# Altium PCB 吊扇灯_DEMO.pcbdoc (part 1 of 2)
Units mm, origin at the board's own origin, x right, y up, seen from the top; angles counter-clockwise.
Board outline 117.71 x 71.75 mm, 2 copper layers (Top Layer, Bottom Layer); 71 components, 50 nets, 203 pads, 259 vias.
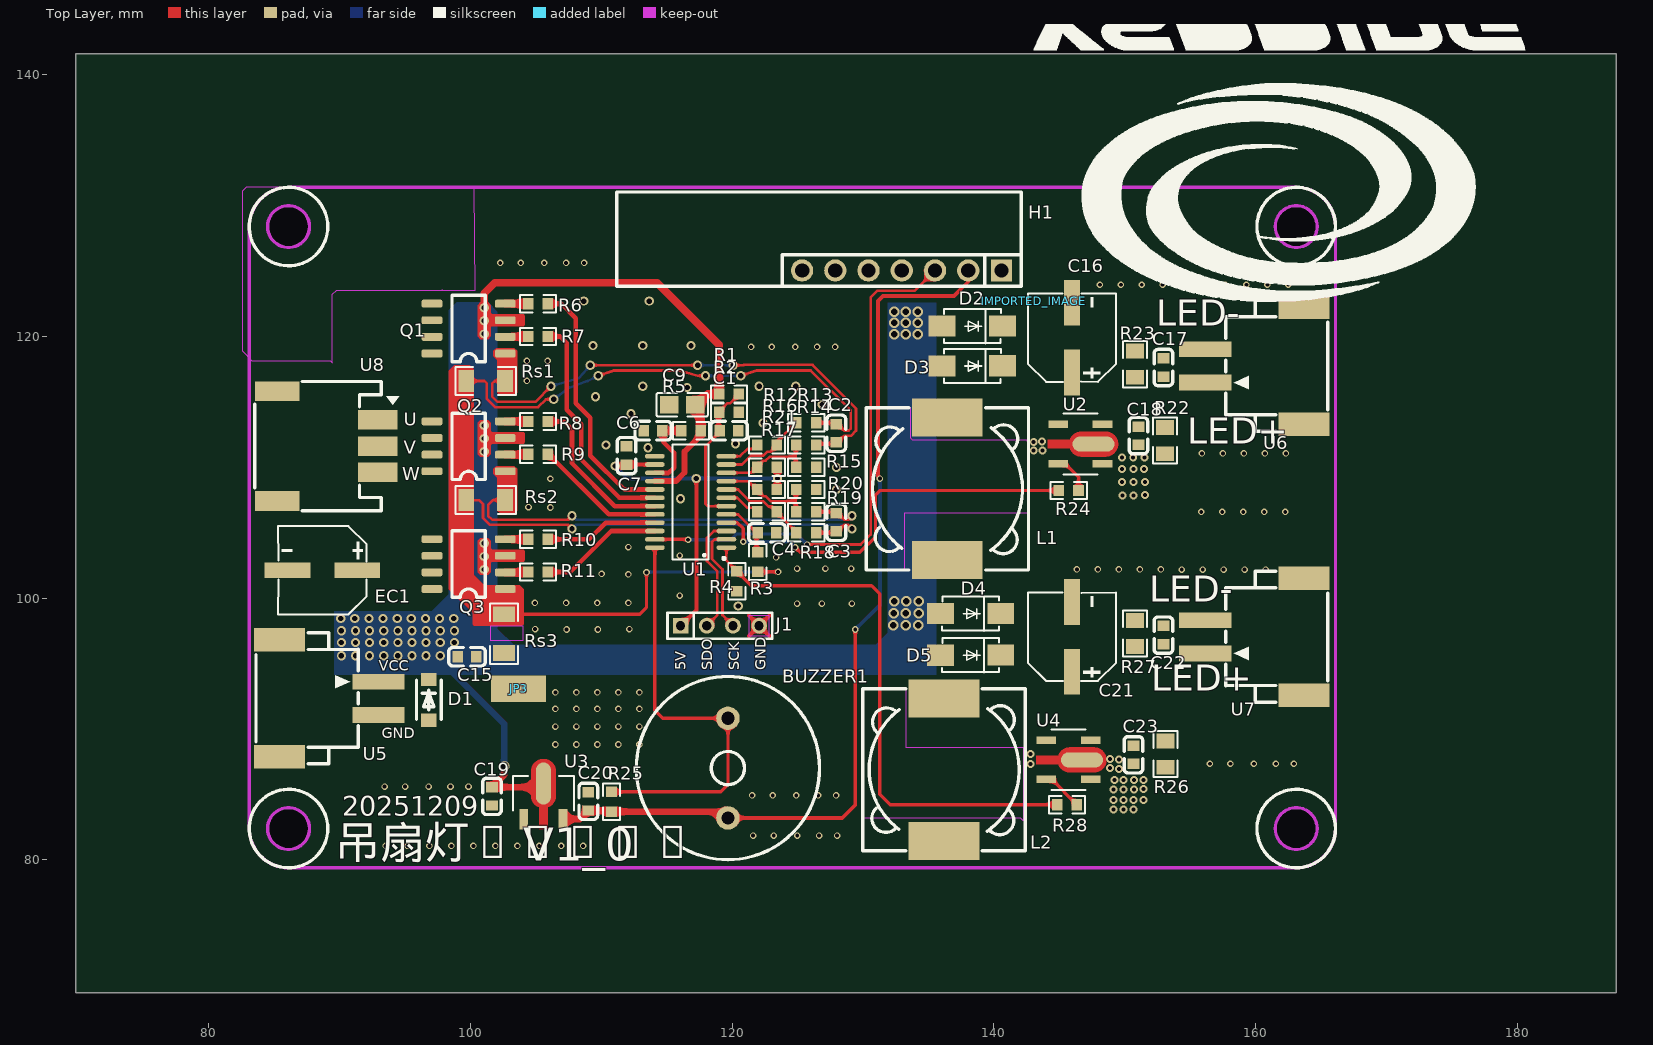
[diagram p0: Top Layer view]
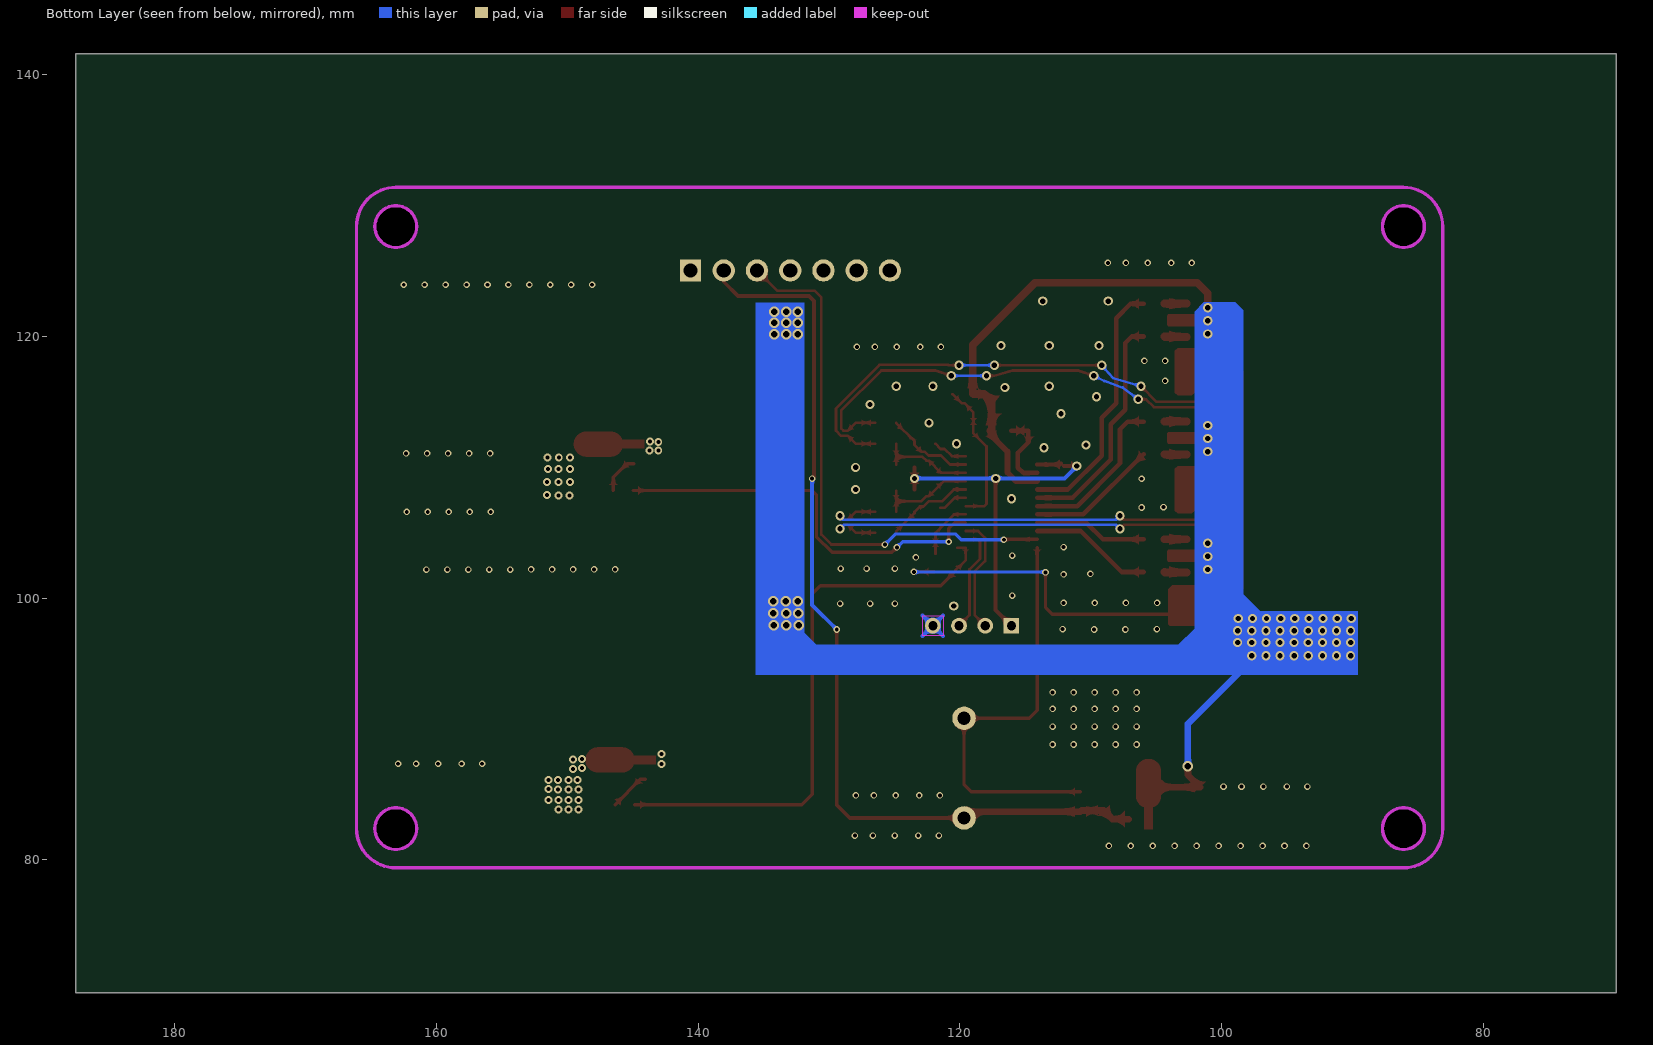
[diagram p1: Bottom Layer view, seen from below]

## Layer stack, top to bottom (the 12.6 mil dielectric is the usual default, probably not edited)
Top Layer: signal copper (thickness not stored)
Dielectric: dielectric 0.32, FR-4, Dk 4.8
Bottom Layer: signal copper (thickness not stored)

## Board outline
187.563,69.85 69.85,69.85 69.85,141.605 187.563,141.605
cut-out: 87.709,128.4 ccw(c86.109,128.392) 84.509,128.4 ccw(c86.109,128.409)
cut-out: 87.709,82.4 ccw(c86.109,82.392) 84.509,82.4 ccw(c86.109,82.409)
cut-out: 164.709,82.4 ccw(c163.109,82.4) 161.509,82.4 ccw(c163.109,82.4)
cut-out: 164.709,128.4 ccw(c163.109,128.4) 161.509,128.4 ccw(c163.109,128.4)

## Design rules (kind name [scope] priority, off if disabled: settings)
BoardOutlineClearance safeClearance [All] p0: genericclearance=0.254 ignorepadtopadclearanceinfootprint=FALSE except(0: Arc-SplitContinuation Track-SplitContinuation SMDPad-SplitContinuation THPad-SplitContinuation Via-SplitContinuation Fill-SplitContinuation Poly-SplitContinuation Region-SplitContinuation Text-SplitContinuation; 0.3: Track-OutlineEdge SMDPad-OutlineEdge THPad-OutlineEdge Via-OutlineEdge Fill-OutlineEdge Region-OutlineEdge Poly-OutlineEdge Text-OutlineEdge Track-CutoutEdge SMDPad-CutoutEdge THPad-CutoutEdge Via-CutoutEdge Fill-CutoutEdge Region-CutoutEdge)
Clearance safeClearance [(InNet('U1') OR InNet('C3') OR InNet('R26') OR InNet('R25') OR InNet('R24') OR InNet('EC1') OR InNet('TVS1') OR InNet('Rs3') OR InNet('Rs2') OR InNet('Rs1') OR InNet('R21') OR InNet('R20') OR InNet('R19') OR InNet('R18') OR InNet('R17') OR InNet('R16') OR InNet('R15') OR InNet('R14') OR InNet('R13') OR InNet('R12') OR InNet('R11') OR InNet('R10') OR InNet('R9') OR InNet('R8') OR InNet('R7') OR InNet('R6') OR InNet('R4') OR InNet('R3') OR InNet('R2') OR InNet('R1') OR InNet('Q3') OR InNet('Q2') OR InNet('Q1') OR InNet('JP3') OR InNet('J1') OR InNet('INPUT1') OR InNet('C15') OR InNet('C9') OR InNet('C7') OR InNet('C4') OR InNet('C2') OR InNet('C1') OR InNet('J3') OR InNet('J4') OR InNet('J5') OR InNet('LED1') OR InNet('R22') OR InNet('R5') OR InNet('C6') OR InNet('IS1+') OR InNet('IS2+') OR InNet('PGND') OR InNet('GND') OR InNet('SWDCLK') OR InNet('SWDIO') OR InNet('ICOMP_P') OR InNet('AD_UDC') OR InNet('OP1-') OR InNet('OP1+') OR InNet('OP2+') OR InNet('OP2-') OR InNet('OP2O') OR InNet('5VA') OR InNet('IS2-') OR InNet('IS1-') OR InNet('HOU') OR InNet('LOU') OR InNet('HOV') OR InNet('LOV') OR InNet('HOW') OR InNet('LOW') OR InNet('OP1O') OR InNet('$1N32') OR InNet('24V') OR InNet('U') OR InNet('$1N1115') OR InNet('$1N1124') OR InNet('V') OR InNet('$1N1118') OR InNet('$1N1122') OR InNet('W') OR InNet('IBUS+') OR InNet('$1N1121') OR InNet('$1N1123') OR InNet('LED2_PWM') OR InNet('BEE') OR InNet('OUT1') OR InNet('LED_PWM') OR InNet('+5V') OR InNet('$1N3953') OR InNet('$1N4076') OR InNet('$2N526') OR InNet('$2N529') OR InNet('$1N4044') OR InNet('$2N527') OR InNet('$1N4057') OR InNet('$2N528') OR InNet('$1N4328') OR InNet('$2N531'))] p1: gap=0.178 ignorepadtopadclearanceinfootprint=FALSE except(0.152: Track-Track Track-SMDPad SMDPad-SMDPad Track-THPad SMDPad-THPad THPad-THPad Track-Via SMDPad-Via THPad-Via Via-Via Track-Fill SMDPad-Fill THPad-Fill Via-Fill Fill-Fill Track-Poly SMDPad-Poly THPad-Poly Via-Poly Fill-Poly Region-Poly Poly-Poly Track-Text SMDPad-Text THPad-Text Via-Text Fill-Text Region-Text Poly-Text Text-Text; 0.175: Track-Hole SMDPad-Hole THPad-Hole Via-Hole Fill-Hole Region-Hole Poly-Hole Text-Hole Sheet-Hole; 0.3: Track-Region SMDPad-Region THPad-Region Via-Region Fill-Region Region-Region Track-Sheet SMDPad-Sheet THPad-Sheet Via-Sheet Fill-Sheet Region-Sheet Poly-Sheet Text-Sheet)
DiffPairsRouting differentialPair [All] p1: maxuncoupledlength=10 minlimit=5.9843 maxlimit=5.9843 mostfreqgap=5.9843 toplayer_minwidth=5 toplayer_prefwidth=10 toplayer_maxwidth=100 bottomlayer_minwidth=5 bottomlayer_prefwidth=10 bottomlayer_maxwidth=100
PasteMaskExpansion pasteMaskExpansion [All] p1: expansion=0
PlaneConnect innerPlane [All] p1: planeconnectstyle=Relief reliefexpansion=0.508 reliefentries=4 reliefconductorwidth=0.254 reliefairgap=0.254
PolygonConnect copperRegion [All] p1: connectstyle=Relief reliefentries=4 reliefconductorwidth=10 polygonreliefangle="90 Angle" airgapwidth=10
PolygonConnect 直连 [All] p1: connectstyle=Direct reliefentries=4 reliefconductorwidth=10 polygonreliefangle="90 Angle" airgapwidth=10
RoutingVias viaSize [All] p1: viastyle="Through Hole" holewidth=12.0078 minholewidth=11.811 maxholewidth=236.1812 width=24.0158 minwidth=19.685 maxwidth=393.7008
SolderMaskExpansion solderMaskExpansion [All] p1: useseparateexpansions=TRUE expansion=2.0079 expansionbottom=2.0079
Width trackWidth [All] p1: maxlimit=100 minlimit=5 preferedwidth=10

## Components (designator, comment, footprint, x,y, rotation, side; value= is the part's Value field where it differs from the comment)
BUZZER1 "SFN-1407PA7.6" BUZ-TH_BD14.0-P7.60-D0.7 119.685,87.02 r90 top
C1 "102/50V" C0603 119.77,112.801 r0 top
C2 "101/50V" C0603 127.97,112.606 r90 top
C3 "101/50V" C0603 127.97,105.806 r270 top
C4 "102/50V" C0603 122.67,105.001 r0 top
C6 "104/50V" C0603 113.97,112.801 r180 top
C7 "10uF/6.3V" C0603 111.938,110.896 r90 top
C9 "10uF/25V" C0805 116.189,114.782 r0 top
C15 "104/50V" C0603 99.746,95.529 r0 top
C16 "47uF ±20% 50V" CAP-SMD_BD6.3-L6.6-W6.6-FD 145.974,119.913 r90 top
C17 "1uF ±10% 50V" C0603 152.959,117.627 r270 top
C18 "1uF ±10% 50V" C0603 151.054,112.42 r90 top
C19 "1uF ±10% 50V" C0603 101.651,84.861 r90 top
C20 "1uF ±10% 50V" C0603 109.017,84.48 r270 top
C21 "47uF ±20% 50V" CAP-SMD_BD6.3-L6.6-W6.6-FD 145.974,97.053 r90 top
C22 "1uF ±10% 50V" C0603 152.959,97.18 r270 top
C23 "1uF ±10% 50V" C0603 150.673,88.036 r90 top
D1 "SMF24A_C315999" SOD-123F_L2.8-W1.8-LS3.7-RD 96.825,92.227 r270 top
D2 "SS36_C7420367" SMA_L4.3-W2.6-LS5.0-FD 138.354,120.802 r0 top
D3 "SS36_C7420367" SMA_L4.3-W2.6-LS5.0-FD 138.354,117.754 r0 top
D4 "SS36_C7420367" SMA_L4.3-W2.6-LS5.0-FD 138.227,98.831 r0 top
D5 "SS36_C7420367" SMA_L4.3-W2.6-LS5.0-FD 138.227,95.656 r0 top
EC1 "100uF ±20% 35V" CAP-SMD_BD6.3-L6.6-W6.6-LS7.2-FD 88.697,102.133 r180 top
H1 "433Mhz模块" 433Mhz 140.589,125.044 r180 top
IMPORTED_IMAGE "IMPORTED_IMAGE" IMPORTED_IMAGE 143.053,122.682 r0 top
J1 "CON4" SIP4-2.0 116.07,97.901 r0 top
JP3 "NC,网络阻断用" JP3.0 103.684,93.087 r180 top
L1 "SMDRI127-470MT" IND-SMD_L12.3-W12.3 136.449,108.356 r270 top
L2 "SMDRI127-470MT" IND-SMD_L12.3-W12.3 136.195,86.893 r270 top
Q1 "AP4606B" SOP8 99.87,120.601 r180 top
Q2 "AP4606B" SOP8 99.87,111.601 r180 top
Q3 "AP4606B" SOP8 99.87,102.601 r180 top
R1 "10K,1%" R0603 119.77,115.601 r0 top
R2 "2K,1%" R0603 119.77,114.201 r0 top
R3 "2K" R0603 121.971,102.768 r270 top
R4 "20K" R0603 120.37,101.301 r270 top
R5 "20R" R0603 116.87,112.801 r180 top
R6 "20R" R0603 105.17,122.501 r180 top
R7 "20R" R0603 105.17,120.001 r180 top
R8 "20R" R0603 105.17,113.501 r180 top
R9 "20R" R0603 105.17,111.001 r180 top
R10 "20R" R0603 105.17,104.501 r180 top
R11 "20R" R0603 105.17,102.001 r180 top
R12 "10K,1%" R0603 122.67,111.706 r0 top
R13 "1K,1%" R0603 125.67,113.406 r0 top
R14 "1K,1%" R0603 125.67,111.706 r0 top
R15 "20K,1%" R0603 125.67,110.006 r0 top
R16 "20K,1%" R0603 122.67,110.006 r180 top
R17 "10K,1%" R0603 122.67,106.606 r0 top
R18 "1K,1%" R0603 125.67,105.006 r0 top
R19 "1K,1%" R0603 125.67,106.606 r0 top
R20 "20K,1%" R0603 125.67,108.306 r0 top
R21 "20K,1%" R0603 122.67,108.306 r180 top
R22 "0805W8F100LT5E" R0805 153.086,112.039 r90 top
R23 "0805W8F3001T5E" R0805 150.8,117.881 r270 top
R24 "Res_0603" R0603 145.72,108.229 r180 top
R25 "Res_0603" R0603 110.795,84.447 r270 top
R26 "0805W8F100LT5E" R0805 153.137,88.087 r90 top
R27 "0805W8F3001T5E" R0805 150.8,97.307 r270 top
R28 "Res_0603" R0603 145.593,84.226 r180 top
Rs1 "0.05R" R1206 101.17,116.601 r180 top
Rs2 "0.05R" R1206 101.17,107.501 r180 top
Rs3 "0.05R" R1206 102.57,97.301 r270 top
U1 "YS32MD220_SSOP24" SSOP-24_L8.7-W3.9-P0.635 116.835,107.359 r90 top
U2 "Hi4315H" SOT-89-5_L4.5-W2.5-P1.50-LS4.5-TL 146.609,111.785 r0 top
U3 "HT7550-1_C16106" SOT-89-3_L4.5-W2.5-P1.50-LS4.2-BR 105.588,84.48 r270 top
U4 "Hi4315H" SOT-89-5_L4.5-W2.5-P1.50-LS4.5-TL 145.72,87.655 r0 top
U5 "2.54-2AWTB" CONN-SMD_2P-P2.54_XH2.54-2AWT 89.205,92.354 r270 top
U6 "2.54-2AWTB" CONN-SMD_2P-P2.54_XH2.54-2AWT 159.944,117.754 r90 top
U7 "2.54-2AWTB" CONN-SMD_2P-P2.54_XH2.54-2AWT 159.944,97.053 r90 top
U8 "BX-HY2.0-3PWT" CONN-SMD_3P-P2.0_BX-HY2.0-3PWT 89.078,111.625 r270 top

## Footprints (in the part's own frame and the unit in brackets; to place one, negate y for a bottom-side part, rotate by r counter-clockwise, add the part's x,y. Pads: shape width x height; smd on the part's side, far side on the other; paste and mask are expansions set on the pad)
433Mhz [mm]
  rect 1.575x1.7 hole 1.1: 1(0,0)
  round 1.7 hole 1.1: 2(2.54,0) 3(5.08,0) 4(7.62,0) 5(10.16,0) 6(12.7,0) 7(15.24,0)
  silkscreen extent -1.52,-6 29.39,1.21
BUZ-TH_BD14.0-P7.60-D0.7 [mm]
  round 1.8 hole 1: 1(-3.81,0) 2(3.81,0)
  silkscreen extent -7,-7 7,7
C0603 [mm]
  rect 0.8x0.9 smd: 1(-0.7,0) 2(0.7,0)
  silkscreen extent -1.39,-0.71 1.39,0.71
C0805 [mm]
  rect 1.41x1.35 smd: 1(-1,0) 2(1,0)
  silkscreen extent -1.96,-0.9 1.96,0.9
CAP-SMD_BD6.3-L6.6-W6.6-FD [mm]
  rect 3.5x1.2 smd: 1(-2.67,0) 2(2.67,0)
  silkscreen extent -3.38,-3.38 3.38,3.38
CAP-SMD_BD6.3-L6.6-W6.6-LS7.2-FD [mm]
  rect 3.5x1.2 smd: 1(-2.67,0) 2(2.67,0)
  silkscreen extent -3.38,-3.38 3.38,3.38
CONN-SMD_2P-P2.54_XH2.54-2AWT [mm]
  rect 1.2x4 smd: 1(-1.27,3.775) 2(1.27,3.775)
  rect 1.8x3.9 smd: 3(4.47,-3.775) 4(-4.47,-3.775)
  silkscreen extent -5,-5.58 5,2.22
CONN-SMD_3P-P2.0_BX-HY2.0-3PWT [mm]
  rect 1.5x3 smd: 1(-2,3.85) 2(0,3.85) 3(2,3.85)
  rect 1.5x3.4 smd: 4(4.2,-3.85) 5(-4.2,-3.85)
  silkscreen extent -4.94,-5.55 4.94,5.5
IMPORTED_IMAGE [mm]
  silkscreen extent 0,0 37.54,22.91
IND-SMD_L12.3-W12.3 [mm]
  rect 2.9x5.4 smd: 1(-5.45,0) 2(5.45,0)
  silkscreen extent -6.2,-6.2 6.2,6.2
JP3.0 [mm]
  rect 2.2x2 smd: 1(-1,0) 2(1,0)
R0603 [mm]
  rect 0.806x0.864 smd: 1(-0.753,0) 2(0.753,0)
  silkscreen extent -1.39,-0.66 1.39,0.66
R0805 [mm]
  rect 1.133x1.377 smd: 1(-1,0) 2(1,0)
  silkscreen extent -1.76,-0.92 1.76,0.92
R1206 [mm]
  rect 1.208x1.701 smd: 1(-1.479,0) 2(1.479,0)
  silkscreen extent -2.31,-1.08 2.31,1.08
SIP4-2.0 [mm]
  rect 1.2x1.2 hole 0.7: 1(0,0)
  round 1.2 hole 0.7: 2(2,0) 3(4,0) 4(6,0)
  silkscreen extent -1,-1 7,1
SMA_L4.3-W2.6-LS5.0-FD [mm]
  rect 2.046x1.62 smd: 1(-2.304,-0.009) 2(2.304,0.009)
  silkscreen extent -2.17,-1.32 2.19,1.29
SOD-123F_L2.8-W1.8-LS3.7-RD [mm]
  rect 1x1.2 smd: 1(-1.55,0) 2(1.55,0)
  silkscreen extent -1.52,-0.93 1.49,0.95
SOP8 [mm]
  rrect50% 1.6x0.6 smd: 1(-2.8,1.9) 2(-2.8,0.63) 3(-2.8,-0.64) 4(-2.8,-1.91) 5(2.8,-1.91) 6(2.8,-0.64) 7(2.8,0.63) 8(2.8,1.9)
  silkscreen extent -1.26,-2.54 1.28,2.54
SOT-89-3_L4.5-W2.5-P1.50-LS4.2-BR [mm]
  rect 1.575x0.672 smd: 1(1.356,-1.5) 3(1.356,1.5)
  oval 3.226x1.14 smd: 2(-1.356,0)
  Top Layer region: -2.283,0.95 -0.429,0.95 -0.384,0.949 -0.34,0.946 -0.296,0.94 -0.252,0.933 -0.208,0.924 -0.165,0.912 -0.123,0.899 -0.081,0.884 -0.04,0.866 0,0.847 0.04,0.826 0.078,0.803 0.115,0.779 0.151,0.752 0.185,0.724 0.219,0.695 0.251,0.664 0.281,0.631 0.31,0.597 0.337,0.562 0.362,0.525 0.386,0.488 0.408,0.449 0.428,0.409 0.447,0.33 2.144,0.33 2.144,-0.33 0.447,-0.33 0.428,-0.409 0.408,-0.449 0.386,-0.488 0.362,-0.526 0.337,-0.562 0.31,-0.597 0.281,-0.631 0.251,-0.664 0.219,-0.695 0.185,-0.725 0.151,-0.753 0.115,-0.779 0.078,-0.804 0.04,-0.827 0,-0.848 -0.04,-0.867 -0.081,-0.884 -0.123,-0.899 -0.165,-0.913 -0.208,-0.924 -0.252,-0.934 -0.296,-0.941 -0.34,-0.946 -0.384,-0.949 -0.429,-0.95 -2.283,-0.95 -2.328,-0.949 -2.372,-0.946 -2.416,-0.941 -2.46,-0.934 -2.504,-0.924 -2.547,-0.913 -2.589,-0.899 -2.631,-0.884 -2.672,-0.867 -2.713,-0.848 -2.752,-0.827 -2.79,-0.804 -2.827,-0.779 -2.863,-0.753 -2.898,-0.725 -2.931,-0.695 -2.963,-0.664 -2.993,-0.631 -3.022,-0.597 -3.049,-0.562 -3.075,-0.526 -3.098,-0.488 -3.12,-0.449 -3.141,-0.409 -3.159,-0.369 -3.175,-0.327 -3.189,-0.285 -3.202,-0.242 -3.212,-0.199 -3.22,-0.155 -3.227,-0.111 -3.231,-0.067 -3.233,-0.022 -3.233,0.022 -3.231,0.067 -3.227,0.111 -3.22,0.155 -3.212,0.199 -3.202,0.242 -3.189,0.285 -3.175,0.327 -3.159,0.369 -3.141,0.409 -3.12,0.449 -3.098,0.488 -3.075,0.525 -3.049,0.562 -3.022,0.597 -2.993,0.631 -2.963,0.664 -2.931,0.695 -2.898,0.724 -2.863,0.752 -2.827,0.779 -2.79,0.803 -2.752,0.826 -2.713,0.847 -2.672,0.866 -2.631,0.884 -2.589,0.899 -2.547,0.912 -2.504,0.924 -2.46,0.933 -2.416,0.94 -2.372,0.946 -2.328,0.949
  silkscreen extent -1.95,-2.33 0.7,2.33
SOT-89-5_L4.5-W2.5-P1.50-LS4.5-TL [mm]
  rect 1.5x0.574 smd: 1(-1.697,1.5) 3(-1.697,-1.5) 4(1.697,-1.5) 5(1.697,1.5)
  oval 3.226x1.14 smd: 2(1.015,-0.009)
  Top Layer region: 1.942,-0.959 0.088,-0.959 0.043,-0.958 -0.001,-0.955 -0.046,-0.949 -0.089,-0.942 -0.133,-0.933 -0.176,-0.921 -0.219,-0.908 -0.26,-0.893 -0.301,-0.875 -0.342,-0.856 -0.381,-0.835 -0.419,-0.812 -0.456,-0.788 -0.492,-0.761 -0.527,-0.733 -0.56,-0.704 -0.592,-0.673 -0.622,-0.64 -0.651,-0.606 -0.678,-0.571 -0.704,-0.534 -0.728,-0.497 -0.749,-0.458 -0.77,-0.418 -0.788,-0.339 -2.485,-0.339 -2.485,0.321 -0.788,0.321 -0.77,0.401 -0.749,0.44 -0.728,0.479 -0.704,0.517 -0.678,0.553 -0.651,0.589 -0.622,0.622 -0.592,0.655 -0.56,0.686 -0.527,0.716 -0.492,0.744 -0.456,0.77 -0.419,0.795 -0.381,0.818 -0.342,0.839 -0.301,0.858 -0.26,0.875 -0.219,0.891 -0.176,0.904 -0.133,0.915 -0.089,0.925 -0.046,0.932 -0.001,0.937 0.043,0.94 0.088,0.941 1.942,0.941 1.986,0.94 2.031,0.937 2.075,0.932 2.119,0.925 2.163,0.915 2.206,0.904 2.248,0.891 2.29,0.875 2.331,0.858 2.371,0.839 2.41,0.818 2.449,0.795 2.486,0.77 2.522,0.744 2.556,0.716 2.59,0.686 2.621,0.655 2.652,0.622 2.681,0.589 2.708,0.553 2.733,0.517 2.757,0.479 2.779,0.44 2.799,0.401 2.817,0.36 2.834,0.318 2.848,0.276 2.86,0.234 2.871,0.19 2.879,0.146 2.885,0.102 2.89,0.058 2.892,0.014 2.892,-0.031 2.89,-0.076 2.885,-0.12 2.879,-0.164 2.871,-0.208 2.86,-0.251 2.848,-0.294 2.834,-0.336 2.817,-0.377 2.799,-0.418 2.779,-0.458 2.757,-0.497 2.733,-0.534 2.708,-0.571 2.681,-0.606 2.652,-0.64 2.621,-0.673 2.59,-0.704 2.556,-0.733 2.522,-0.761 2.486,-0.788 2.449,-0.812 2.41,-0.835 2.371,-0.856 2.331,-0.875 2.29,-0.893 2.248,-0.908 2.206,-0.921 2.163,-0.933 2.119,-0.942 2.075,-0.949 2.031,-0.955 1.986,-0.958
  silkscreen extent -1.3,-2.33 1.3,2.33
SSOP-24_L8.7-W3.9-P0.635 [mil]
  oval 14x59.25 smd: 1(-137.5,-107.68) 2(-112.5,-107.68) 3(-87.5,-107.68) 4(-62.5,-107.68) 5(-37.5,-107.68) 6(-12.5,-107.68) 7(12.5,-107.68) 8(37.5,-107.68) 9(62.5,-107.68) 10(87.5,-107.68) 11(112.5,-107.68) 12(137.5,-107.68) 13(137.5,107.68) 14(112.5,107.68) 15(87.5,107.68) 16(62.5,107.68) 17(37.5,107.68) 18(12.5,107.68) 19(-12.5,107.68) 20(-37.5,107.68) 21(-62.5,107.68) 22(-87.5,107.68) 23(-112.5,107.68) 24(-137.5,107.68)
  silkscreen extent -174,-104 173,54

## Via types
v1: diameter 0.5, hole 0.3, Top Layer to Bottom Layer, 124 vias
v2: diameter 0.7, hole 0.4, Top Layer to Bottom Layer, 79 vias
v3: diameter 0.61, hole 0.305, Top Layer to Bottom Layer, 37 vias
v4: diameter 0.8, hole 0.5, Top Layer to Bottom Layer, 19 vias

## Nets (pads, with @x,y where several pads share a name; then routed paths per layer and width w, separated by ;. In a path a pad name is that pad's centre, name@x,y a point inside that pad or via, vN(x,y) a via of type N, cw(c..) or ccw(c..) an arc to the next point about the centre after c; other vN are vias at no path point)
5VA: C7.1 J1.1 R16.1 R21.1 U1.14 | length 29.1
  Top Layer w0.3: v2(111.07,110.101) C7.1@112.07,110.101 ; C7.1@112.27,110.301 112.355,110.216 U1.14@114.1,110.216 ; J1.1@116.07,97.901 117.27,99.101 v2(117.27,109.156) ; R21.1@123.47,108.306 v2(123.47,109.156) R16.1@123.47,110.006
  Bottom Layer w0.3: v2(111.07,110.101) 112.015,109.156 v2(117.27,109.156) v2(123.47,109.156)
24V: C9.2 C15.1 C19.2 D1.1 D2.1 D4.1 EC1.1 Q1.3 Q2.3 Q3.3 R1.1 R5.1 U1.16 U3.2 U5.1 | length 51.8
  Top Layer w0.45: U1.16@114.1,108.946 115.715,108.946 116.37,109.601 116.37,111.201 117.67,112.501 R5.1@117.67,112.801
  Top Layer w0.5: v4(102.591,87.147) 102.591,86.501 C19.2@101.651,85.561 105.312,85.561 U3.2@105.588,85.837
  Top Layer w0.6: v2(101.07,122.201) 101.07,123.301 101.87,124.101 114.27,124.101 119.02,119.351 119.02,115.651 118.97,115.601 118.17,115.601 117.57,115.001 117.57,114.401 117.57,112.901 R5.1@117.67,112.801
  Bottom Layer w0.5: v2@97.46,95.529 102.591,90.399 v4(102.591,87.147)
  other v2: 90.145,95.606 91.224,95.606 92.304,95.606 93.383,95.606 94.463,95.606 95.542,95.606 96.622,95.606 97.701,95.606 90.145,96.622 91.224,96.622 92.304,96.622 93.383,96.622 94.463,96.622 95.542,96.622 96.622,96.622 97.701,96.622 98.781,96.622 90.145,97.511 91.224,97.511 92.304,97.511 93.383,97.511 94.463,97.511 95.542,97.511 96.622,97.511 97.701,97.511 98.781,97.511 90.094,98.45 91.173,98.45 92.253,98.45 93.332,98.45 94.412,98.45 95.491,98.45 96.571,98.45 97.65,98.45 98.73,98.45 101.07,102.201 101.07,103.201 101.07,104.201 101.07,111.201 101.07,112.201 101.07,113.201 101.07,120.201 101.07,121.201
  other v4: 132.309,97.942 133.26,97.942 134.236,97.942 132.353,98.855 133.277,98.855 134.271,98.855 132.41,99.771 133.295,99.771 134.271,99.771 132.41,120.166 133.274,120.174 134.174,120.166 134.174,121.034 132.41,121.056 133.274,121.056 132.41,121.895 133.268,121.895 134.174,121.895
$1N32: C6.1 R5.2 U1.15 | length 6.1
  Top Layer w0.35: U1.15@114.1,109.581 115.17,109.581 115.57,109.981 115.57,111.101 114.77,111.901 114.77,112.801 R5.2@116.07,112.801
$1N1115: Q1.2 R7.2 | length 1.7
  Top Layer w0.6: Q1.2@102.67,119.971 104.34,119.971 R7.2@104.37,120.001
$1N1118: Q2.2 R9.2 | length 1.7
  Top Layer w0.6: Q2.2@102.67,110.971 104.34,110.971 R9.2@104.37,111.001
$1N1121: Q3.2 R11.2 | length 1.7
  Top Layer w0.6: Q3.2@102.67,101.971 104.34,101.971 R11.2@104.37,102.001
$1N1122: Q2.4 R8.2 | length 1.7
  Top Layer w0.6: Q2.4@102.67,113.511 104.36,113.511 R8.2@104.37,113.501
$1N1123: Q3.4 R10.2 | length 1.7
  Top Layer w0.6: Q3.4@102.67,104.511 104.36,104.511 R10.2@104.37,104.501
$1N1124: Q1.4 R6.2 | length 1.7
  Top Layer w0.6: Q1.4@102.67,122.511 104.36,122.511 R6.2@104.37,122.501
$1N3953: C16.1 C17.2 D2.2 D3.2 R23.2 U6.1
$1N4044: D3.1 L1.1 U2.1
$1N4057: L1.2 R22.1 U2.4
$1N4076: C17.1 C18.2 R22.2 R23.1 U2.5 U6.2
$1N4328: R24.1 U2.3 | length 3
  Top Layer w0.254: U2.3@144.911,110.285 145.442,110.285 146.482,109.245 146.482,108.238 R24.1@146.473,108.229
$2N526: C21.1 C22.2 D4.2 D5.2 R27.2 U7.1
$2N527: D5.1 L2.1 U4.1
$2N528: L2.2 R26.1 U4.4
$2N529: C22.1 C23.2 R26.2 R27.1 U4.5 U7.2
$2N531: R28.1 U4.3 | length 3.1
  Top Layer w0.254: U4.3@144.022,86.155 144.417,86.155 R28.1@146.346,84.226
+5V: BUZZER1.1 C20.2 H1.2 R25.2 U3.3 | length 71
  Top Layer w0.3: BUZZER1.1@119.685,83.21 128.422,83.21 129.413,84.201 v1(129.413,97.612) ; v1(131.293,109.144) 131.14,109.296 131.14,122.707 131.521,123.088 136.957,123.088 138.049,124.181 H1.2@138.049,125.044
  Top Layer w0.5: U3.3@107.088,83.124 108.361,83.124 C20.2@109.017,83.78 110.708,83.78 R25.2@110.795,83.694 119.201,83.694 BUZZER1.1@119.685,83.21
  Bottom Layer w0.3: v1(129.413,97.612) 131.293,99.492 v1(131.293,109.144)
AD_UDC: C1.1 R1.2 R2.1 U1.6 | length 11.3
  Top Layer w0.2: U1.6@119.57,107.041 118.13,107.041 117.97,107.201 117.97,111.601 118.97,112.601 118.97,114.201 119.67,114.901 119.87,114.901 R1.2@120.57,115.601
BEE: BUZZER1.2 R25.1 U1.24 | length 32.5
  Top Layer w0.254: R25.1@110.795,85.201 119.135,85.201 119.685,85.75 BUZZER1.2@119.685,90.831 114.706,90.831 114.1,91.437 U1.24@114.1,103.866
GND: C1.2 C4.2 C6.2 C7.2 C9.1 C16.2 C18.1 C19.1 C20.1 C21.2 C23.1 H1.1 J1.4 JP3.1 R2.2 R4.2 R15.2 R20.2 U1.13 U2.2 U3.1 U4.2 U6.3 U6.4 U7.3 U7.4 | length 8.9
  Top Layer w0.3: 121.285,97.117 J1.4@122.07,97.901 ; 121.285,98.686 J1.4@122.07,97.901 ; 122.854,97.117 J1.4@122.07,97.901 ; 122.854,98.686 J1.4@122.07,97.901
  Bottom Layer w0.3: 121.285,98.686 J1.4@122.07,97.901 ; 121.287,97.119 J1.4@122.07,97.901 ; 122.854,97.117 J1.4@122.07,97.901 ; 122.854,98.686 J1.4@122.07,97.901
  other v1: 93.523,81.077 95.201,81.077 96.879,81.077 98.557,81.077 100.235,81.077 101.913,81.077 103.591,81.077 105.269,81.077 106.946,81.077 108.624,81.077 121.615,81.864 123.184,81.864 124.979,81.864 126.653,81.864 128.03,81.864 121.539,84.938 123.107,84.938 124.903,84.938 126.577,84.938 127.954,84.938 93.447,85.598 95.015,85.598 96.811,85.598 98.484,85.598 99.861,85.598 156.515,87.351 158.083,87.351 159.879,87.351 161.552,87.351 162.93,87.351 106.502,88.824 108.106,88.824 109.71,88.824 111.313,88.824 112.917,88.824 106.502,90.195 108.106,90.195 109.71,90.195 111.313,90.195 112.917,90.195 106.502,91.542 108.106,91.542 109.71,91.542 111.313,91.542 112.917,91.542 106.502,92.812 108.106,92.812 109.71,92.812 111.313,92.812 112.917,92.812 107.354,97.612 109.754,97.612 104.953,97.638 112.155,97.638 124.968,99.593 126.859,99.593 129.16,99.593 104.927,99.644 107.313,99.644 109.699,99.644 112.085,99.644 116.002,100.206 112.085,101.827 110.033,101.854 154.364,102.184 155.965,102.184 157.567,102.184 159.169,102.184 160.771,102.184 146.355,102.21 147.957,102.21 149.558,102.21 151.16,102.21 152.762,102.21 124.968,102.26 127.138,102.26 129.108,102.26 123.368,103.124 116.002,103.251 112.085,103.902 155.854,106.604 157.458,106.604 159.062,106.604 160.666,106.604 162.269,106.604 106.114,106.934 104.445,106.959 106.114,109.132 155.905,111.074 157.509,111.074 159.113,111.074 160.716,111.074 162.32,111.074 104.318,116.611 104.318,118.138 105.913,118.138 121.463,119.202 123.031,119.202 124.827,119.202 126.5,119.202 127.878,119.202 148.107,123.952 149.706,123.952 151.305,123.952 152.904,123.952 154.503,123.952 156.102,123.952 157.701,123.952 159.3,123.952 160.899,123.952 162.498,123.952 102.286,125.628 103.854,125.628 105.65,125.628 107.323,125.628 108.701,125.628
  other v2: 120.47,99.401 116.07,107.601 127.97,108.301 127.97,110.001 113.57,111.501 110.37,111.701 120.27,111.801 122.37,113.401 112.27,114.101 126.87,114.801 109.57,115.401 116.57,116.101 113.17,116.201 122.07,116.201 124.87,116.201 109.37,119.301 113.17,119.301 116.87,119.301 108.67,122.701 113.67,122.701
  other v3: 149.149,83.845 149.905,83.845 150.684,83.845 149.161,84.568 149.917,84.568 150.684,84.568 151.439,84.568 149.161,85.382 149.905,85.382 150.73,85.382 151.439,85.417 151.439,86.102 149.219,86.125 149.928,86.125 150.73,86.125 149.556,86.956 148.895,87.02 142.799,87.321 149.556,87.66 148.895,87.7 142.799,88.083 149.819,107.848 150.673,107.848 151.547,107.877 149.784,108.864 150.671,108.864 151.547,108.864 149.784,109.88 150.674,109.88 151.493,109.88 149.784,110.769 150.656,110.769 151.5,110.769 143.053,111.277 143.713,111.294 143.053,111.949 143.688,111.963
HOU: R6.1 U1.17 | length 19.5
  Top Layer w0.35: R6.1@105.97,122.501 106.97,122.501 108.07,121.401 108.07,114.901 109.17,113.801 109.17,110.901 111.76,108.311 U1.17@114.1,108.311
HOV: R8.1 U1.19 | length 12.3
  Top Layer w0.35: R8.1@105.97,113.501 107.17,113.501 107.77,112.901 107.77,110.301 111.03,107.041 U1.19@114.1,107.041
HOW: R10.1 U1.21 | length 8.7
  Top Layer w0.35: R10.1@105.97,104.501 109.07,104.501 110.34,105.771 U1.21@114.1,105.771
IBUS+: Q3.1 R3.2 Rs1.2 Rs2.2 Rs3.1 | length 26.7
  Top Layer w0.2: Rs2.2@100.17,107.501 100.57,107.501 ; Rs1.2@100.17,116.601 101.07,116.601
  Top Layer w0.254: Rs3.1@102.57,98.78 112.953,98.78 113.462,99.289 v1(113.462,101.981) ; R3.2@121.971,102.015 123.512,102.015 v1(123.52,102.006)
  Bottom Layer w0.254: v1(113.462,101.981) 113.487,102.006 v1(123.52,102.006)
ICOMP_P: C4.1 R3.1 U1.5 | length 4.5
  Top Layer w0.2: U1.5@119.57,106.406 120.465,106.406 121.87,105.001 R3.1@121.87,103.401
IS1+: C2.1 Q1.1 R14.2 Rs1.1 | length 37.6
  Top Layer w0.2: Rs1.1@102.67,116.601 101.87,116.601 101.67,116.401 101.67,115.401 102.07,115.001 104.97,115.001 v2(106.17,116.201) ; v2(109.17,117.801) v2(117.37,117.801) v2@117.57,117.801 ; v2@120.27,117.801 120.856,117.801 120.882,117.828 126.143,117.828 129.47,114.501 129.47,112.806 129.07,112.406 128.57,112.406 127.97,111.806 R14.2@126.47,111.806
  Bottom Layer w0.2: v2(106.17,116.201) 108.27,116.801 v2(109.17,117.801) ; v2(117.37,117.801) v2(120.07,117.801)
IS1-: C2.2 R13.2 | length 36
  Top Layer w0.2: 101.07,116.601 101.27,116.401 101.27,115.236 101.904,114.601 105.17,114.601 105.77,115.201 v2(106.37,115.201) ; v2(109.77,117.001) 110.97,117.401 115.97,117.401 117.37,117.001 v2(117.97,117.001) ; v2(120.67,117.001) 121.87,117.401 126.004,117.401 129.07,114.336 129.07,112.972 128.904,112.806 128.57,112.806 127.97,113.406 R13.2@126.47,113.406
  Bottom Layer w0.2: v2(106.37,115.201) 107.57,116.101 108.97,116.601 v2(109.77,117.001) ; v2(117.97,117.001) v2(120.67,117.001)
IS2+: C3.1 Q2.1 R19.2 Rs2.1 | length 33.6
  Top Layer w0.2: Rs2.1@102.67,107.501 101.73,107.501 101.37,107.141 101.37,106.301 101.67,106.001 107.47,106.001 v2(107.77,106.301) ; R19.2@126.47,106.606 127.97,106.606 128.575,106.001 128.87,106.001 v2(129.17,106.301)
  Bottom Layer w0.2: v2(107.77,106.301) 108.07,106.001 128.92,106.001 v2@129.17,106.251
IS2-: C3.2 R18.2 | length 33.4
  Top Layer w0.2: 100.67,107.501 100.97,107.201 100.97,106.136 101.504,105.601 107.47,105.601 v2(107.77,105.301) ; R18.2@126.47,105.006 127.97,105.006 128.565,105.601 128.87,105.601 v2(129.17,105.301)
  Bottom Layer w0.2: v2(107.77,105.301) 108.07,105.601 128.87,105.601 v2(129.17,105.301)
LED2_PWM: R4.1 R28.2 U1.1 | length 43.6
  Top Layer w0.2: U1.1@120.205,103.866 U1.1@119.57,103.866 119.57,102.901 R4.1@120.37,102.101
  Top Layer w0.254: R4.1@120.37,102.055 121.46,100.965 130.658,100.965 131.293,100.33 131.293,85.014 132.08,84.226 R28.2@144.839,84.226
LED_PWM: R24.2 U1.4 | length 30.8
  Top Layer w0.254: U1.4@119.57,105.771 120.416,105.771 120.853,105.334 v1(120.853,104.318) ; v1(124.816,103.886) 125.197,103.505 129.769,103.505 130.962,104.699 130.962,107.925 131.267,108.229 R24.2@144.966,108.229
  Bottom Layer w0.254: v1(120.853,104.318) 124.384,104.318 v1(124.816,103.886)
LOU: R7.1 U1.18 | length 17.8
  Top Layer w0.35: R7.1@105.97,120.001 106.87,120.001 107.37,119.501 107.37,114.401 108.47,113.301 108.47,110.601 111.395,107.676 U1.18@114.1,107.676
LOV: R9.1 U1.20 | length 10
  Top Layer w0.35: R9.1@105.97,111.001 110.565,106.406 U1.20@114.1,106.406
LOW: R11.1 U1.22 | length 9.4
  Top Layer w0.35: R11.1@105.97,102.001 107.635,102.001 110.77,105.136 U1.22@114.1,105.136
OP1+: R19.1 R20.1 R21.2 U1.9 | length 7.5
  Top Layer w0.2: U1.9@119.57,108.946 121.23,108.946 122.37,107.806 122.56,107.806 122.96,107.406 124.87,107.406 ; R19.1@124.87,106.606 124.87,107.406 ; R20.1@124.87,108.206 124.87,107.406
OP1-: R17.2 R18.1 U1.8 | length 6.7
  Top Layer w0.2: U1.8@119.57,108.311 120.465,108.311 121.37,107.406 122.394,107.406 122.794,107.006 123.07,107.006 R17.2@123.47,106.606 ; R17.2@123.47,106.506 124.87,105.106 R18.1@124.87,105.006
OP1O: R17.1 U1.7 | length 2.3
  Top Layer w0.2: U1.7@119.57,107.676 120.4,107.676 121.17,106.906 121.501,106.906
OP2+: R14.1 R15.1 R16.2 U1.10 | length 7.4
  Top Layer w0.2: U1.10@119.57,109.581 121.445,109.581 122.37,110.506 122.57,110.506 122.87,110.806 124.87,110.806 ; R15.1@124.87,110.206 124.87,110.806 ; R14.1@124.87,111.806 124.87,110.806
OP2-: R12.2 R13.1 U1.11 | length 6.8
  Top Layer w0.2: U1.11@119.57,110.216 120.756,110.216 121.446,110.906 122.394,110.906 122.694,111.206 122.97,111.206 123.47,111.706 123.47,112.006 R13.1@124.87,113.406
OP2O: R12.1 U1.12 | length 2.7
  Top Layer w0.2: U1.12@119.57,110.851 120.625,110.851 121.18,111.406 121.47,111.406 R12.1@121.87,111.806
OUT1: H1.3 U1.23 | length 41.2
  Top Layer w0.2: v1(125.743,104.102) 129.83,104.102 130.583,104.856 130.583,122.989 131.089,123.495 133.96,123.495 H1.3@135.509,125.044
  Top Layer w0.254: U1.23@114.1,104.501 116.606,104.501 v1(116.637,104.47)
  Bottom Layer w0.254: v1(116.637,104.47) 119.888,104.47 120.32,104.902 124.943,104.902 v1(125.743,104.102)
PGND: C15.2 D1.2 EC1.2 JP3.2 Rs3.2 U5.2 U5.3 U5.4 U8.4 U8.5
SWDCLK: J1.3 U1.2 | length 8.2
  Top Layer w0.2: U1.2@119.57,104.501 118.67,104.501 118.47,104.301 118.47,103.001 119.27,102.201 119.27,98.701 J1.3@120.07,97.901
SWDIO: J1.2 U1.3 | length 9.1
  Top Layer w0.2: J1.2@118.07,97.901 118.87,98.701 118.87,102.036 118.07,102.836 118.07,104.601 118.605,105.136 U1.3@119.57,105.136
U: Q1.5 Q1.6 Q1.7 Q1.8 U8.1
V: Q2.5 Q2.6 Q2.7 Q2.8 U8.2
W: Q3.5 Q3.6 Q3.7 Q3.8 U8.3
pads on no net: H1.4 H1.5 H1.6 H1.7
copper on no net: | length 0.1
  Top Layer w0.2: 100.57,107.501 100.67,107.501

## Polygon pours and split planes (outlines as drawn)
GND on Bottom Layer (solid, remove dead copper, pour order 38): 80.086,135.255 167.716,135.255 167.716,76.2 80.086,76.2
GND on Top Layer (solid, remove dead copper, pour order 36): 76.2,133.579 169.088,133.579 169.088,77.089 76.2,77.089
PGND on Top Layer (solid, remove dead copper, pour order 0): 103.684,96.682 103.684,90.196 100.381,86.893 83.475,86.893 83.161,87.207 83.161,117.829 83.109,117.881 87.935,117.881 87.935,92.588 88.395,92.127 99.138,92.127 100,92.989 100,96.291 100.39,96.682
W on Top Layer (solid, remove dead copper, pour order 2): 89.967,110.388 89.967,106.07 90.348,105.689 92.126,105.689 95.809,102.006 95.809,100.482 96.19,100.101 97.841,100.101 97.968,100.228 97.968,107.975 97.587,108.356 96.698,108.356 94.666,110.388
V on Top Layer (solid, remove dead copper, pour order 4): 90.094,112.547 95.174,112.547 95.555,112.928 95.555,113.817 95.936,114.198 97.841,114.198 97.841,109.218 97.615,108.991 96.444,108.991 94.793,110.642 90.094,110.642
U on Top Layer (solid, remove dead copper, pour order 6): 90.094,112.928 94.539,112.928 94.92,113.309 94.92,114.071 95.428,114.579 97.833,114.579 97.833,123.108 89.859,123.108 89.84,123.088 89.84,113.182
24V on Top Layer (solid, remove dead copper, pour order 8): 89.459,102.768 89.459,92.862 89.713,92.608 98.603,92.608 99.466,93.471 99.466,98.223 98.476,99.212 96.063,99.212 95.047,100.228 95.047,101.498 93.777,102.768
$2N527 on Top Layer (solid, remove dead copper, pour order 10): 133.759,96.799 136.77,96.799 143.12,90.449 144.577,90.449 145.085,89.941 145.085,88.953 144.93,88.798 133.655,88.798 133.528,88.925 133.528,96.568
$2N526 on Top Layer (solid, remove dead copper, pour order 12): 139.234,100.107 139.234,94.776 141.656,92.354 157.785,92.354 158.293,92.862 158.293,96.291 158.039,96.545 158.039,96.672 157.658,97.053 144.196,97.053 143.561,97.688 143.561,99.593 143.047,100.107
$2N529 on Top Layer (solid, remove dead copper, pour order 14): 146.609,88.798 160.299,88.798 161.175,89.674 161.175,98.871 160.452,99.593 149.53,99.593 149.53,97.434 158.462,97.434 158.829,97.114 158.829,92.382 158.293,91.846 146.609,91.846
$2N528 on Top Layer (solid, remove dead copper, pour order 16): 153.975,87.274 153.975,79.654 153.848,79.527 130.099,79.527 129.972,79.654 129.972,83.043 151.395,83.043 152.324,83.972 152.324,87.274
GND on Top Layer (solid, remove dead copper, pour order 18): 142.418,88.418 142.418,86.766 148.26,86.766 148.641,86.385 148.641,83.344 151.314,83.344 152.07,84.099 152.07,87.401 151.562,87.909 150.165,87.909 149.657,88.417 143.307,88.417
$2N528 on Top Layer (solid, remove dead copper, pour order 20): 146.609,85.178 147.244,84.543 147.244,82.547 148.342,82.547 148.342,86.43 148.26,86.512 146.736,86.512 146.609,86.385
$1N4044 on Top Layer (solid, remove dead copper, pour order 22): 133.528,118.135 134.036,118.643 138.354,118.643 138.481,118.516 138.481,116.484 140.005,114.96 145.339,114.96 145.804,114.495 145.804,112.986 145.148,112.547 139.817,112.547 139.448,112.178 133.77,112.178 133.528,112.42
$1N3953 on Top Layer (solid, remove dead copper, pour order 24): 139.361,121.833 139.361,116.62 140.64,115.341 158.293,115.341 158.801,115.849 158.801,116.992 158.388,117.405 149.879,117.405 147.625,119.659 144.323,119.659 142.149,121.833
$1N4076 on Top Layer (solid, remove dead copper, pour order 26): 146.736,113.055 149.276,113.055 149.784,112.547 160.452,112.547 161.341,113.436 161.341,120.04 160.325,121.056 150.165,121.056 149.53,120.421 149.53,118.514 150.162,117.881 158.928,117.881 159.436,117.373 159.436,115.468 158.796,114.829 146.858,114.829 146.736,114.706
$1N4057 on Top Layer (solid, remove dead copper, pour order 28): 149.149,110.642 147.453,110.642 147.453,107.168 146.863,106.578 133.147,106.578 133.147,106.436 133.147,101.498 143.18,101.498 145.593,103.911 153.213,103.911 154.229,104.927 154.229,111.337 154.003,111.563 152.262,111.563 152.262,106.897 152.07,106.705 149.657,106.705 149.149,107.213
GND on Top Layer (solid, remove dead copper, pour order 30): 142.649,112.344 151.556,112.344 151.886,112.013 151.886,107.157 151.689,106.959 150.038,106.959 149.403,107.594 149.403,110.568 149.038,111.023 142.799,111.023 142.649,111.173
24V on Top Layer (solid, remove dead copper, pour order 32): 131.953,97.384 136.703,97.384 136.728,97.409 136.728,100.254 136.652,100.33 131.953,100.33 131.877,100.254 131.877,97.46
24V on Top Layer (solid, remove dead copper, pour order 34): 131.902,122.453 137.287,122.453 137.287,119.1 131.874,119.1 131.902,119.488

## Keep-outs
Top Layer:
  region: 101.555,97.901 103.988,97.901 103.988,96.749 101.555,96.749
  region: 142.237,83.011 142.066,83.182 130.078,83.182 129.995,83.265 129.995,93.094 133.255,93.094 133.274,93.075 133.274,88.598 142.237,88.598
  region: 130.273,114.507 133.557,114.507 133.604,114.554 133.604,112.268 133.756,112.116 142.469,112.116 142.57,112.014 142.57,106.629 142.723,106.477 133.147,106.477 133.147,102.235 133.096,102.184 130.302,102.184 130.251,102.235 130.273,102.257
  region: 100.387,123.52 100.305,131.4 82.886,131.4 82.575,131.089 82.575,118.897 83.312,118.161 89.281,118.161 89.459,117.983 89.459,123.215 89.789,123.546 97.815,123.546 97.841,123.571 97.841,123.52
Board Outline Layer:
  circle w0.025: c86.109,128.4 r1.6
  circle w0.254: c86.109,128.4 r1.6
  circle w0.025: c86.109,82.4 r1.6
  circle w0.254: c86.109,82.4 r1.6
  circle w0.025: c163.109,82.4 r1.6
  circle w0.254: c163.109,82.4 r1.6
  circle w0.025: c163.109,128.4 r1.6
  circle w0.254: c163.109,128.4 r1.6
  region: 121.292,98.679 121.292,97.124 122.848,97.124 122.848,98.679
  lines w0.254: 83.109,82.4 ccw(c86.109,82.4) 86.109,79.4 163.109,79.4 ccw(c163.109,82.4) 166.109,82.4 166.109,128.4 ccw(c163.109,128.4) 163.109,131.4 86.109,131.4 ccw(c86.109,128.4) 83.109,128.4 83.109,82.4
